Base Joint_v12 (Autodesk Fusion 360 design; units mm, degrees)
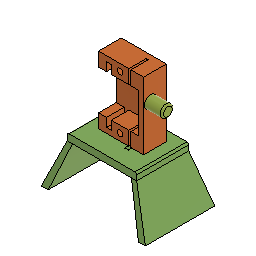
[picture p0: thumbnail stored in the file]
component_insert "Component Insert1"
component_insert "Component Insert4"
component_insert "Component Insert5"
joint "Assemble" alignAngle 0 alignOffsetX 0 alignOffsetY 5.85 (= "( ( 30 - 18.3 ) / 2 ) * 1 mm") alignOffsetZ 0
component_insert "Component Insert6"
joint "Assemble" alignAngle 180 alignOffsetX 0 alignOffsetY 0 alignOffsetZ 0
remove_instance "RemoveInstance1"
joint "Assemble" alignAngle 180 alignOffsetX 9.15 (= "( 18.3 / 2 ) * 1 mm") alignOffsetY -24.55 (= "-( 20.9 mm + ( 7.3 / 2 ) * 1 mm )") alignOffsetZ 0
